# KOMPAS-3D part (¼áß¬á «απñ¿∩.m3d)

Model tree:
1. Эскиз:1
2. Операция выдавливания:1
     Расстояние 1 = 3.9; Расстояние 2 = 3.2
3. Эскиз:2
4. Операция выдавливания:2
     Расстояние 1 = 2; Расстояние 2 = 3.2
5. Эскиз:3
6. Операция выдавливания:3
     Расстояние 1 = 3.8; Угол 1 = 47; Расстояние 2 = 3.2
7. Эскиз:4
8. Операция выдавливания:4
     Расстояние 1 = 7.9; Расстояние 2 = 3.2
9. Фаска:1
     Угол = 45; Длина 1 = 1; Длина 2 = 1
10. Эскиз:5
11. Отверстие:1
12. Эскиз:7
13. Вырезать элемент выдавливания:2
     Расстояние 2 = 14.8; Расстояние 1 = 14.8
14. Эскиз:8
15. Вырезать элемент выдавливания:3
     Расстояние 1 = 20.8
16. Эскиз:9
17. Операция выдавливания:5
     Расстояние 1 = 15; Расстояние 2 = 7.2
18. Эскиз:14
19. Операция выдавливания:7
     Расстояние 1 = 40
20. Эскиз:15
21. Вырезать элемент выдавливания:7
     Расстояние 2 = 4; Расстояние 1 = 22
22. Эскиз:16
23. Вырезать элемент выдавливания:8
     Расстояние 2 = 4; Расстояние 1 = 2
24. Эскиз:17
25. Вырезать элемент выдавливания:9
     Расстояние 2 = 4; Расстояние 1 = 20.8
26. Эскиз:18
27. Операция выдавливания:8
     Расстояние 1 = 3
28. Смещенная плоскость:1
     Расстояние = 10
29. Эскиз:20
30. Операция выдавливания:9
     Расстояние 1 = 4; Расстояние 2 = 4
31. Эскиз:21
32. Операция выдавливания:10
     Расстояние 1 = 4; Расстояние 2 = 6
33. Скругление:1
     Радиус = 2

Referenced files in C:\Program Files\ASCON\KOMPAS-3D V13 Home\Sys\: holelib.lfr
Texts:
  stalker61
  Сплав АЛ8  ГОСТ 1583-93
  Отверстие 01
  (вариант 1)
